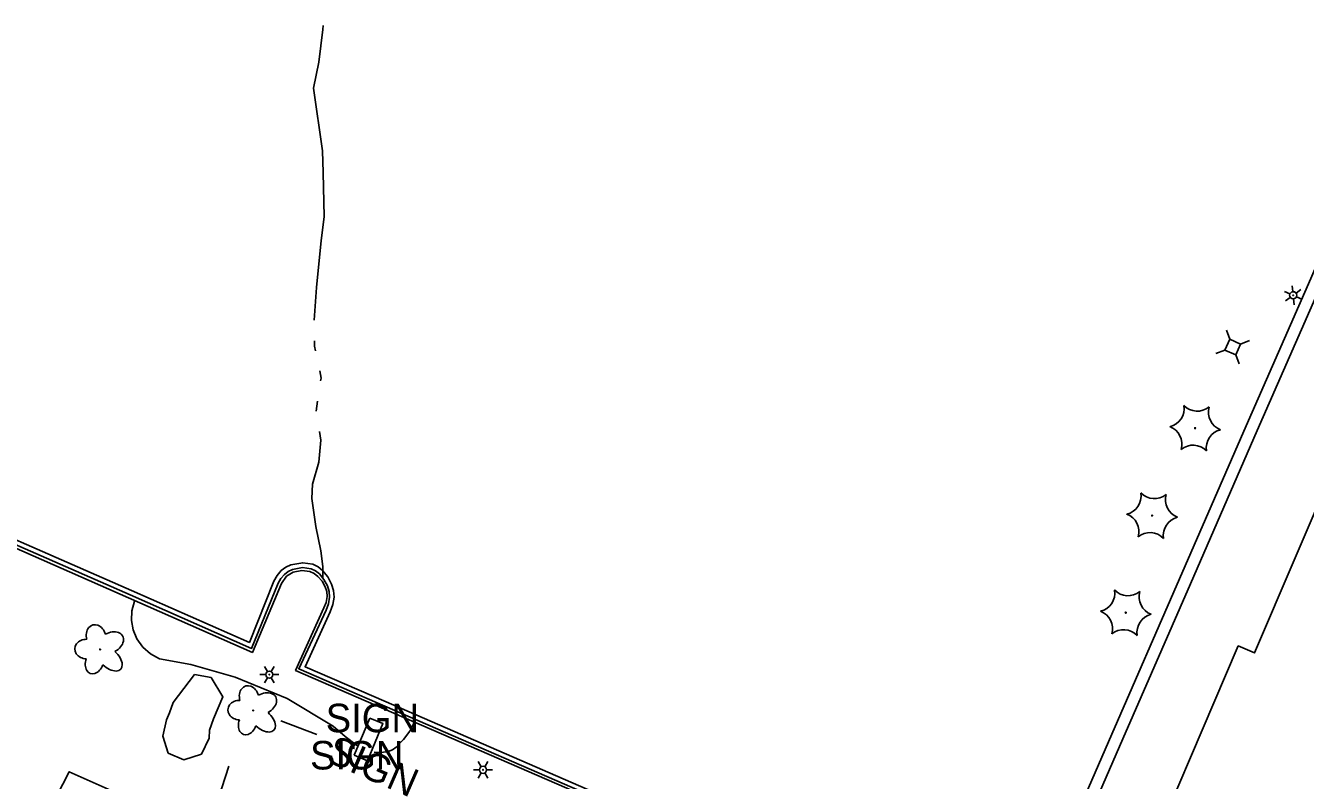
# Model space of a CAD drawing. Extents: x 588843 to 2552415, y 180129 to 269402.
# Drawn here: x 594447 to 594716.2, y 185413.8 to 185572.7 of the extents above; entities that cross this region are included whole.
import ezdxf

# ---------------------------------------------------------------- set-up
doc = ezdxf.new("R2010")
doc.units = 0
for name, color, linetype in [('Default', 7, 'Continuous'), ('E_BLD', 7, 'Continuous'), ('E_DRN_RipRap', 7, 'Continuous'), ('E_DWY', 7, 'Continuous'), ('E_LAND_Vegetation', 7, 'Continuous'), ('E_LTG', 7, 'Continuous'), ('E_MISCPROP_Planter', 7, 'Continuous'), ('E_RDWY_C_and_G', 7, 'Continuous'), ('E_RDWY_Gravel', 7, 'Continuous'), ('E_SGN', 7, 'Continuous'), ('E_SGN_Text', 7, 'Continuous'), ('E_UTL_AG_Bold', 7, 'Continuous'), ('E_WTR_P', 7, 'Continuous')]:
    doc.layers.add(name, color=color, linetype=linetype)

# ---------------------------------------------------------------- blocks, each defined once
blk = doc.blocks.new('LPOL_1_1')
at = {"layer": 'Default'}
for p, q in [((-4, 0), (-1.5, 0)), ((-0.75, 1.3), (-2, 3.46)), ((0.75, 1.3), (2, 3.46)), ((1.5, 0), (4, 0)), ((-2, -3.46), (-0.75, -1.3)), ((2, -3.46), (0.75, -1.3))]:
    blk.add_line(p, q, dxfattribs=at)
for radius in [1.5, 1.5, 1.5, 0.125]:
    blk.add_circle((0, 0), radius, dxfattribs=at)
blk = doc.blocks.new('DTRE_1_1')
at = {"layer": 'Default'}
blk.add_circle((-0.18, 0), 0.183, dxfattribs=at)
for centre, major_axis, ratio in [((-1.87, 5.32), (1.36, -4.98), 0.782863), ((4.06, 2.74), (-5.27, -2.93), 0.691916), ((-5.87, 0.15), (4.93, -0.12), 0.832022), ((-2.49, -5.24), (1.8, 4.86), 0.716896), ((3.54, -3.71), (-5.01, 4.58), 0.560249)]:
    blk.add_ellipse(centre, major_axis=major_axis, ratio=ratio, start_param=1.570796, end_param=4.712389, dxfattribs=at)
blk = doc.blocks.new('BSGN_1')
at = {"layer": 'Default'}
blk.add_text('SIGN', height=12, dxfattribs=at).set_placement((-18.56, -6))
blk = doc.blocks.new('SIGN_3')
at = {"layer": 'E_SGN'}
blk.add_text('SIGN', height=39.37, dxfattribs=at).set_placement((-56.1, -19.7))
blk = doc.blocks.new('LPOL_5')
at = {"layer": 'E_LTG'}
for p, q in [((-13.1, 0), (-4.9, 0)), ((-2.5, 4.3), (-6.6, 11.4)), ((2.5, 4.3), (6.6, 11.4)), ((4.9, 0), (13.1, 0)), ((-6.6, -11.4), (-2.5, -4.3)), ((6.6, -11.4), (2.5, -4.3))]:
    blk.add_line(p, q, dxfattribs=at)
for radius in [4.92, 4.92, 4.92, 0.41]:
    blk.add_circle((0, 0), radius, dxfattribs=at)
blk = doc.blocks.new('PED_4')
at = {"layer": 'E_UTL_AG_Bold'}
for p, q in [((-8.2, 8.2), (-17.5, 17.5)), ((8.2, 8.2), (17.5, 17.5)), ((-8.2, -8.2), (-17.5, -17.5)), ((8.2, -8.2), (17.5, -17.5))]:
    blk.add_line(p, q, dxfattribs=at)
blk.add_lwpolyline([(-8.2, -8.2), (8.2, -8.2), (8.2, 8.2), (-8.2, 8.2)], close=True, dxfattribs=at)
blk = doc.blocks.new('CTRE_5')
at = {"layer": 'E_LAND_Vegetation'}
blk.add_circle((0, 0), 0.733, dxfattribs=at)
for centre, start, end in [((-39.3, 29.4), 280.2067, 5.9716), ((5.9, 49), 220.2113, 305.9762), ((45.4, 19.3), 160.2113, 245.9762), ((-45.4, -19.3), 340.2113, 65.9762), ((39.5, -29.6), 100.2511, 185.9272), ((-5.9, -49), 40.2113, 125.9762)]:
    blk.add_arc(centre, 25.8, start, end, dxfattribs=at)

msp = doc.modelspace()

# ---------------------------------------------------------------- linework, layer by layer
at = {"layer": 'E_BLD'}
msp.add_lwpolyline([(594720.92, 185371.72), (594679.49, 185389.41), (594702.02, 185442.16), (594705.46, 185440.69), (594722.35, 185480.22), (594762.62, 185463.02), (594741.76, 185414.17), (594739.47, 185415.15)], close=True, dxfattribs=at)
at = {"layer": 'E_DRN_RipRap'}
msp.add_lwpolyline([(594486, 185435.48), (594482.51, 185436.13), (594478.02, 185430.27), (594477.24, 185428.07), (594476.62, 185426.56), (594475.88, 185423.18), (594476.98, 185419.6), (594480.29, 185418.19), (594483.96, 185419.34), (594485.56, 185422.71), (594485.66, 185424.45), (594486.5, 185426.82), (594488.5, 185431.43)], close=True, dxfattribs=at)
at = {"layer": 'E_DWY'}
for points in [[(594726.85, 185541.54), (594717.32, 185519.48), (594703.73, 185488.45), (594689.69, 185456.24), (594675.43, 185423.6), (594663.05, 185395.04)], [(594729.14, 185540.55), (594719.61, 185518.48), (594706.02, 185487.45), (594691.98, 185455.24), (594677.73, 185422.6), (594665.34, 185394.04)]]:
    msp.add_lwpolyline(points, dxfattribs=at)
at = {"layer": 'E_MISCPROP_Planter'}
for points in [[(594469.86, 185451.59), (594469.34, 185449.5), (594469.26, 185447.49), (594469.61, 185445.52), (594470.38, 185443.67), (594470.38, 185443.67), (594471.62, 185441.89), (594473.24, 185440.45), (594475.15, 185439.41), (594475.15, 185439.41), (594481.7, 185438.27), (594491.03, 185435.58), (594502.02, 185431.1), (594511.68, 185425.27), (594514.19, 185423.06), (594516.77, 185421.11)], [(594520.27, 185419.81), (594521.77, 185419.74), (594523.25, 185419.92), (594523.25, 185419.92), (594524.16, 185420.25), (594524.95, 185420.82), (594524.95, 185420.82), (594526.49, 185422.44), (594526.49, 185422.44), (594527.59, 185423.9), (594527.59, 185423.9), (594528.05, 185424.66), (594528.05, 185424.66), (594528.58, 185425.76), (594528.58, 185425.76)]]:
    msp.add_lwpolyline(points, dxfattribs=at)
at = {"layer": 'E_RDWY_C_and_G'}
for points in [[(594421.83, 185473.5), (594468.97, 185452.93), (594494.52, 185441.61), (594500.12, 185455.37), (594500.69, 185456.35), (594501.42, 185457.2), (594501.42, 185457.2), (594502.2, 185457.81), (594503.09, 185458.23), (594503.09, 185458.23), (594505.21, 185458.65), (594505.21, 185458.65), (594507.03, 185458.4), (594507.03, 185458.4), (594507.97, 185457.97), (594508.78, 185457.31), (594508.78, 185457.31), (594509.73, 185456.13), (594510.46, 185454.81), (594510.46, 185454.81), (594510.83, 185453.63), (594510.91, 185452.39), (594510.91, 185452.39), (594510.68, 185451), (594510.17, 185449.68), (594510.17, 185449.68), (594504.42, 185437.35), (594522.51, 185429.45), (594570.95, 185408.42)], [(594422.13, 185474.44), (594469.27, 185453.8), (594494.05, 185442.87), (594499.19, 185455.81), (594499.87, 185456.98), (594500.76, 185457.99), (594500.76, 185457.99), (594501.7, 185458.71), (594502.77, 185459.21), (594502.77, 185459.21), (594505.28, 185459.66), (594505.28, 185459.66), (594507.39, 185459.34), (594507.39, 185459.34), (594508.49, 185458.81), (594509.43, 185458.04), (594509.43, 185458.04), (594510.52, 185456.68), (594511.35, 185455.15), (594511.35, 185455.15), (594511.77, 185453.82), (594511.86, 185452.42), (594511.86, 185452.42), (594511.61, 185450.84), (594511.05, 185449.34), (594511.05, 185449.34), (594505.75, 185437.78), (594522.79, 185430.4), (594571.3, 185409.27)], [(594421.94, 185472.83), (594468.6, 185452.24), (594494.69, 185440.77), (594500.78, 185455.27), (594501.87, 185456.8), (594501.87, 185456.8), (594503.25, 185457.67), (594503.25, 185457.67), (594505.05, 185458.02), (594505.05, 185458.02), (594506.78, 185457.8), (594506.78, 185457.8), (594507.69, 185457.4), (594508.48, 185456.79), (594508.48, 185456.79), (594509.34, 185455.77), (594510.01, 185454.61), (594510.01, 185454.61), (594510.33, 185453.6), (594510.38, 185452.53), (594510.38, 185452.53), (594510.17, 185451.31), (594509.7, 185450.17), (594509.7, 185450.17), (594503.78, 185437.01), (594522.32, 185428.92), (594570.87, 185407.9)]]:
    msp.add_lwpolyline(points, dxfattribs=at)
at = {"layer": 'E_RDWY_Gravel'}
msp.add_lwpolyline([(594348.92, 185439.79), (594369.96, 185429.46), (594383.73, 185421.69), (594397.97, 185413.82), (594446.4, 185394.86), (594449.62, 185401.06), (594450.88, 185405.43), (594456.18, 185415.68), (594467.5, 185410.59), (594464.66, 185399.74), (594464.07, 185391.84), (594466.01, 185388.04), (594494.93, 185369.91), (594541.17, 185349.71)], dxfattribs=at)
at = {"layer": 'E_SGN'}
msp.add_line((594500.68, 185426.36), (594508.25, 185423.48), dxfattribs=at)
for points in [[(594519.38, 185426.98), (594522.15, 185425.82), (594518.86, 185417.99), (594516.09, 185419.15)], [(594519.38, 185426.98), (594516.09, 185419.15)]]:
    msp.add_lwpolyline(points, dxfattribs=at)
at = {"layer": 'E_WTR_P'}
for points in [[(594509.56, 185572.7), (594509.51, 185571.9), (594508.69, 185565.03), (594507.56, 185559.5), (594509.42, 185546.35), (594509.55, 185541.78)], [(594509.55, 185541.78), (594509.81, 185532.48), (594509.18, 185527.5), (594508.18, 185517.58), (594507.64, 185510.68)], [(594507.71, 185506.38), (594507.74, 185505.21), (594507.96, 185504.25)], [(594508.85, 185500.04), (594509.14, 185498.5), (594509.04, 185497.92)], [(594508.37, 185493.67), (594508.13, 185491.53)], [(594508.77, 185487.29), (594509.08, 185485.44), (594508.68, 185480.85), (594507.35, 185476.19), (594507.16, 185473.15), (594508.01, 185467.29), (594509.07, 185462.17), (594509.49, 185458.83), (594509.52, 185456.53)], [(594489.73, 185416.87), (594488.22, 185412.29), (594485.18, 185404.83), (594483.78, 185400.62), (594483.43, 185398.01), (594483.46, 185393.88), (594484.98, 185389.03), (594485.98, 185387.51)]]:
    msp.add_lwpolyline(points, dxfattribs=at)

# ---------------------------------------------------------------- block references
at = {"layer": 'E_LAND_Vegetation', "xscale": 0.15240030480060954, "yscale": 0.15240030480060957, "rotation": 3.4338469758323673}
for p in [(594692.97, 185487.97), (594683.91, 185469.57), (594678.38, 185449.14)]:
    msp.add_blockref('CTRE_5', p, dxfattribs=at)
at = {"layer": 'E_LAND_Vegetation', "xscale": 0.5, "yscale": 0.5}
for p in [(594462.73, 185441.41), (594494.93, 185428.57)]:
    msp.add_blockref('DTRE_1_1', p, dxfattribs=at)
at = {"layer": 'E_LTG', "xscale": 0.1524003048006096, "yscale": 0.1524003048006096, "rotation": -23.954644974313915}
msp.add_blockref('LPOL_5', (594713.59, 185515.95), dxfattribs=at)
at = {"layer": 'E_LTG', "xscale": 0.5, "yscale": 0.5}
for p in [(594498.24, 185436.11), (594543.19, 185416.07)]:
    msp.add_blockref('LPOL_1_1', p, dxfattribs=at)
at = {"layer": 'E_SGN', "xscale": 0.5, "yscale": 0.5}
for p in [(594519.38, 185426.98), (594516.09, 185419.15)]:
    msp.add_blockref('BSGN_1', p, dxfattribs=at)
at = {"layer": 'E_SGN_Text', "xscale": 0.1524003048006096, "yscale": 0.15240030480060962, "rotation": -23.490092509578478}
msp.add_blockref('SIGN_3', (594518.89, 185417.36), dxfattribs=at)
at = {"layer": 'E_UTL_AG_Bold', "xscale": 0.15240030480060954, "yscale": 0.15240030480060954, "rotation": -24.15481473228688}
msp.add_blockref('PED_4', (594700.87, 185505.05), dxfattribs=at)

doc.saveas('drawing.dxf')
